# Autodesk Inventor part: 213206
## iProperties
Company: Mayer & Müller AG Schaltgeräte
Created: 2006-01
Part Number: 213206
Material: PsP 3010
Document SubType Name: Sheet Metal
Designer: I.Baliuc
Manufacturer: Standard
Standards Organization: Custom
Description: Streifen
Density: 7.84 g/cm^3
Sheet Metal Rule: Standard
HalbzeugNorm: DIN 40600
Zweck: Spule
Abmessung: 35x0,3-750
Author: T.Messerschmitt
Keywords: 213206
Revision Number: 213206
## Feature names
1. Extr_35-Breit
